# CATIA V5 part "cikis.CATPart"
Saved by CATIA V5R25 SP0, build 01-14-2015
Part number: giris
Bounding box of the stored display mesh (mm): x 0 to 10, y -12.486 to 237.486, z -12.5 to 12.5
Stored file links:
  C:\Users\Aidata\Downloads\cikis.CATPart
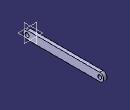
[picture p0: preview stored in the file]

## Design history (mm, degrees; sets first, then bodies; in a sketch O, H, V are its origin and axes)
Body1 (main body)
  Sketch1 on yz-plane, origin (0, 0, 0), H (0, 1, 0), V (0, 0, 1)
    construction line L1 (0, 0) -> (225, 0)
    line L2 (0, 12.5) -> (225, 12.5)
    line L3 (225, -12.5) -> (0, -12.5)
    arc A1 centre (225, 0) radius 12.5 from (225, 12.5) to (225, -12.5) cw
    arc A2 centre (0, 0) radius 12.5 from (0, -12.5) to (0, 12.5) cw
    circle A3 centre (0, 0) radius 6
    circle A4 centre (225, 0) radius 6
    distance L3 L2 = 25
    radius A3 = 6
    radius A4 = 6
    distance A1 A2 = 250
    horizontal: L1 H
    tangency: A1 L2, A2 L2, A1 L3, A2 L3
  Pad1: profile Sketch1, direction (1, 0, 0), length 10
